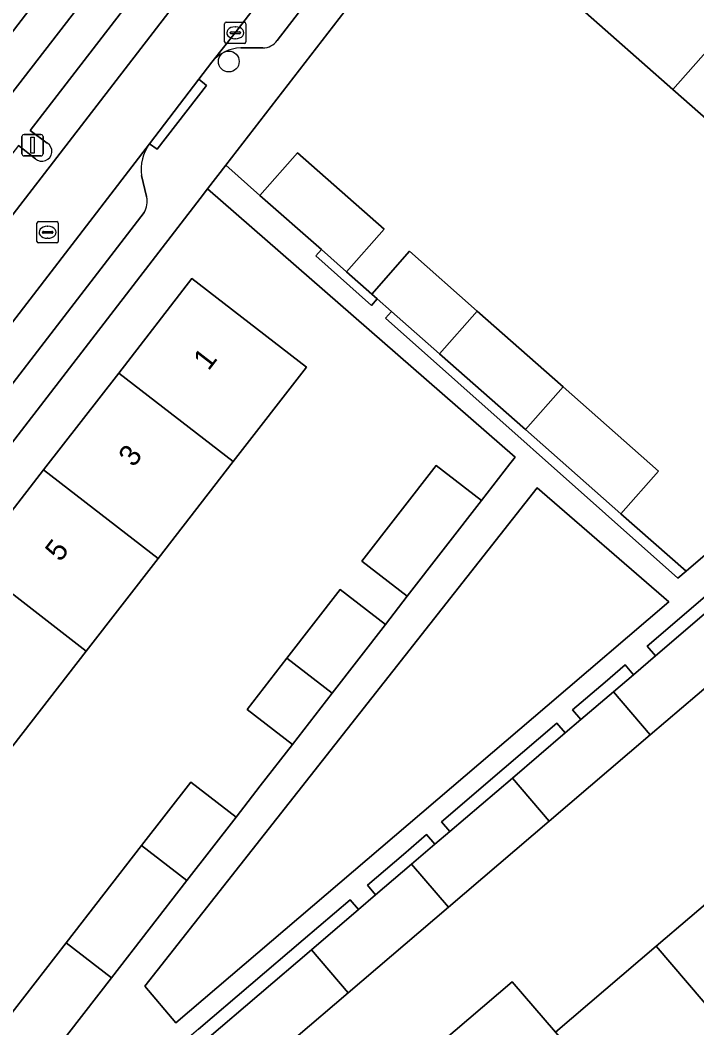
# Model space of a CAD drawing. Extents: x 159039 to 160102, y 381214 to 382524.
# Drawn here: x 159284.46 to 159316.18, y 381529.08 to 381576.34 of the extents above; entities that cross this region are included whole.
import ezdxf

# ---------------------------------------------------------------- set-up
doc = ezdxf.new("R2010")
doc.units = 0
for name, color, linetype in [('IMGEO_Boom', 7, 'Continuous'), ('IMGEO_Erf', 7, 'Continuous'), ('IMGEO_Groenvoorziening', 7, 'Continuous'), ('IMGEO_Kolk', 7, 'Continuous'), ('IMGEO_Lichtmast', 7, 'Continuous'), ('IMGEO_Pand', 7, 'Continuous'), ('IMGEO_Pand_nummerreeks', 7, 'Continuous'), ('IMGEO_Parkeervlak_open', 7, 'Continuous'), ('IMGEO_Rijbaan_lokaal_open', 7, 'Continuous'), ('IMGEO_Rioolput', 7, 'Continuous'), ('IMGEO_Voetpad_open', 7, 'Continuous')]:
    doc.layers.add(name, color=color, linetype=linetype)

msp = doc.modelspace()

# ---------------------------------------------------------------- linework, layer by layer
at = {"layer": 'IMGEO_Boom'}
msp.add_circle((159294.236, 381574.401), 0.489, dxfattribs=at)
at = {"layer": 'IMGEO_Erf'}
for points in [[(159299.551, 381592.96), (159298.091, 381594.079), (159294.348, 381589.194), (159290.532, 381584.215), (159286.641, 381579.137), (159282.958, 381574.331), (159279.168, 381569.384), (159275.191, 381564.195), (159276.512, 381563.173)], [(159284.112, 381542.306), (159280.576, 381537.741), (159277.232, 381533.425), (159271.871, 381537.579), (159275.215, 381541.895), (159278.751, 381546.459), (159282.191, 381550.899), (159285.558, 381555.245), (159289.08, 381559.791), (159292.511, 381564.22), (159297.872, 381560.066), (159294.441, 381555.638), (159290.919, 381551.092), (159287.552, 381546.746)]]:
    msp.add_lwpolyline(points, close=True, dxfattribs=at)
for points in [[(159315.045, 381573.092), (159310.694, 381576.932), (159306.603, 381580.543), (159311.027, 381585.556), (159315.118, 381581.946), (159319.469, 381578.106), (159323.501, 381574.546), (159327.908, 381570.657), (159326.122, 381568.633), (159329.49, 381565.653), (159327.56, 381563.446), (159329.123, 381562.03), (159335.629, 381567.611), (159330.095, 381572.777), (159313.062, 381587.649)], [(159308.113, 381587.579), (159306.856, 381586.072), (159294.094, 381569.533), (159295.697, 381568.119), (159297.465, 381570.121), (159301.524, 381566.539), (159299.757, 381564.536), (159300.936, 381563.495), (159302.703, 381565.499), (159305.875, 381562.699), (159309.907, 381559.139), (159314.377, 381555.194), (159312.61, 381553.192), (159315.671, 381550.49), (159325.662, 381559.061), (159316.821, 381566.857), (159319.159, 381569.462), (159319.078, 381569.533), (159315.045, 381573.092)], [(159296.955, 381546.416), (159299.454, 381549.642), (159301.579, 381547.996), (159302.602, 381549.316), (159300.477, 381550.962), (159303.956, 381555.453), (159306.081, 381553.807), (159307.411, 381555.524), (159307.658, 381555.842), (159293.244, 381568.431), (159292.895, 381567.979), (159271.052, 381539.613)], [(159319.124, 381547.204), (159313.993, 381542.822), (159309.256, 381538.775), (159304.533, 381534.74), (159299.831, 381530.723), (159294.926, 381526.533), (159290.062, 381522.377), (159288.338, 381524.395), (159285.465, 381521.941), (159289.064, 381518.753), (159295.726, 381512.647), (159298.097, 381510.434)], [(159272.188, 381533.437), (159277.302, 381529.172), (159283.05, 381524.08), (159285.339, 381527.035), (159283.214, 381528.681), (159286.611, 381533.065), (159290.148, 381537.63), (159292.453, 381540.606), (159294.578, 381538.96), (159295.713, 381540.424), (159297.219, 381542.368), (159295.094, 381544.014), (159296.955, 381546.416)], [(159318.584, 381527.856), (159313.861, 381523.821), (159309.159, 381519.804), (159304.254, 381515.614), (159299.493, 381511.547), (159295.184, 381516.591), (159299.945, 381520.658), (159304.85, 381524.848), (159302.822, 381527.222), (159307.524, 381531.239), (159309.552, 381528.865), (159314.275, 381532.9), (159319.012, 381536.947)]]:
    msp.add_lwpolyline(points, dxfattribs=at)
at = {"layer": 'IMGEO_Groenvoorziening'}
for points in [[(159299.757, 381564.536), (159298.578, 381565.576), (159298.318, 381565.282), (159300.925, 381562.96), (159301.195, 381563.267), (159300.936, 381563.495)], [(159308.141, 381557.137), (159304.108, 381560.696), (159301.864, 381562.676), (159301.59, 381562.367), (159315.29, 381550.163), (159315.671, 381550.49), (159312.61, 381553.192)], [(159290.297, 381531.025), (159291.758, 381529.315), (159298.155, 381534.78), (159309.155, 381544.179), (159314.868, 381549.06), (159308.694, 381554.412)], [(159317.4, 381549.222), (159319.467, 381550.988), (159319.077, 381551.444), (159317.01, 381549.678), (159313.849, 381546.978), (159314.238, 381546.522)], [(159313.207, 381545.641), (159312.817, 381546.097), (159311.879, 381545.296), (159310.35, 381543.99), (159310.74, 381543.534), (159312.269, 381544.84)], [(159307.532, 381540.793), (159310.01, 381542.911), (159309.621, 381543.367), (159307.142, 381541.249), (159304.211, 381538.745), (159304.601, 381538.289)], [(159303.9, 381537.69), (159303.51, 381538.146), (159302.419, 381537.214), (159300.732, 381535.772), (159301.121, 381535.316), (159302.809, 381536.758)], [(159298.107, 381532.741), (159300.311, 381534.624), (159299.921, 381535.08), (159297.717, 381533.197), (159292.812, 381529.007), (159292.385, 381528.642), (159292.775, 381528.186), (159293.202, 381528.551)]]:
    msp.add_lwpolyline(points, close=True, dxfattribs=at)
at = {"layer": 'IMGEO_Kolk'}
for p, q in [((159294.115, 381576.249), (159294.967, 381576.249)), ((159294.04, 381575.323), (159294.04, 381576.175)), ((159294.342, 381575.792), (159294.74, 381575.792)), ((159294.528, 381576.029), (159294.553, 381576.029)), ((159295.041, 381576.175), (159295.041, 381575.323)), ((159294.299, 381575.743), (159294.299, 381575.755)), ((159294.737, 381575.706), (159294.339, 381575.706)), ((159294.551, 381575.469), (159294.526, 381575.469)), ((159294.783, 381575.755), (159294.783, 381575.743)), ((159294.967, 381575.249), (159294.115, 381575.249))]:
    msp.add_line(p, q, dxfattribs=at)
for points in [[(159294.115, 381576.249), (159294.967, 381576.249)], [(159294.04, 381575.323), (159294.04, 381576.175)], [(159295.041, 381576.175), (159295.041, 381575.323)], [(159294.967, 381575.249), (159294.115, 381575.249)]]:
    msp.add_lwpolyline(points, dxfattribs=at)
for centre, radius, start, end in [((159294.117, 381576.173), 0.0765, 91.552, 178.448), ((159294.117, 381576.173), 0.0765, 91.552, 178.448), ((159294.965, 381576.173), 0.0765, 1.552, 88.448), ((159294.965, 381576.173), 0.0765, 1.552, 88.448), ((159294.339, 381575.752), 0.0403, 85.8775, 175.7526), ((159294.744, 381575.754), 0.0386, 1.7309, 96.639), ((159294.117, 381575.325), 0.0765, 181.552, 268.448), ((159294.117, 381575.325), 0.0765, 181.552, 268.448), ((159294.336, 381575.742), 0.0366, 178.938, 274.7102), ((159294.74, 381575.749), 0.043, 264.8664, 352.4533), ((159294.965, 381575.325), 0.0765, 271.552, 358.448), ((159294.965, 381575.325), 0.0765, 271.552, 358.448)]:
    msp.add_arc(centre, radius, start, end, dxfattribs=at)
for centre, major_axis, ratio, start_param, end_param in [((159294.527, 381575.749), (-0.387, 0.002), 0.722429, 4.712389, 7.853982), ((159294.552, 381575.749), (-0.39, 0.002), 0.717154, 1.570796, 4.712389)]:
    msp.add_ellipse(centre, major_axis=major_axis, ratio=ratio, start_param=start_param, end_param=end_param, dxfattribs=at)
at = {"layer": 'IMGEO_Lichtmast'}
for p, q in [((159284.541, 381570.077), (159284.541, 381570.877)), ((159284.541, 381570.877), (159284.541, 381570.077)), ((159284.641, 381570.977), (159285.431, 381570.977)), ((159285.431, 381570.977), (159284.641, 381570.977)), ((159285.531, 381570.877), (159285.531, 381570.077)), ((159285.531, 381570.077), (159285.531, 381570.877)), ((159285.431, 381569.977), (159284.641, 381569.977)), ((159284.641, 381569.977), (159285.431, 381569.977))]:
    msp.add_line(p, q, dxfattribs=at)
msp.add_lwpolyline([(159284.961, 381570.852), (159285.111, 381570.852), (159285.111, 381570.102), (159284.961, 381570.102), (159284.961, 381570.852)], dxfattribs=at)
for centre, start, end in [((159284.641, 381570.877), 90, 180), ((159284.641, 381570.877), 90, 180), ((159285.431, 381570.877), 0, 90), ((159285.431, 381570.877), 360, 90), ((159284.641, 381570.077), 180, 270), ((159284.641, 381570.077), 180, 270), ((159285.431, 381570.077), 270, 0), ((159285.431, 381570.077), 270, 0)]:
    msp.add_arc(centre, 0.1, start, end, dxfattribs=at)
at = {"layer": 'IMGEO_Pand'}
for points in [[(159282.958, 381574.331), (159286.641, 381579.137), (159281.285, 381583.241), (159277.602, 381578.435)], [(159315.118, 381581.946), (159310.694, 381576.932), (159315.045, 381573.092), (159319.469, 381578.106)], [(159319.078, 381569.533), (159323.501, 381574.546), (159319.469, 381578.106), (159315.045, 381573.092)], [(159297.465, 381570.121), (159295.697, 381568.119), (159298.578, 381565.576), (159299.757, 381564.536), (159301.524, 381566.539)], [(159302.703, 381565.499), (159300.936, 381563.495), (159301.195, 381563.267), (159301.864, 381562.676), (159304.108, 381560.696), (159305.875, 381562.699)], [(159294.441, 381555.638), (159297.872, 381560.066), (159292.511, 381564.22), (159289.08, 381559.791)], [(159305.875, 381562.699), (159304.108, 381560.696), (159308.141, 381557.137), (159309.907, 381559.139)], [(159294.441, 381555.638), (159289.08, 381559.791), (159285.558, 381555.245), (159290.919, 381551.092)], [(159309.907, 381559.139), (159308.141, 381557.137), (159312.61, 381553.192), (159314.377, 381555.194)], [(159302.602, 381549.316), (159306.081, 381553.807), (159303.956, 381555.453), (159300.477, 381550.962)], [(159287.552, 381546.746), (159290.919, 381551.092), (159285.558, 381555.245), (159282.191, 381550.899)], [(159287.552, 381546.746), (159282.191, 381550.899), (159278.751, 381546.459), (159284.112, 381542.306)], [(159301.579, 381547.996), (159299.454, 381549.642), (159296.955, 381546.416), (159299.08, 381544.77)], [(159319.124, 381547.204), (159317.4, 381549.222), (159314.238, 381546.522), (159313.207, 381545.641), (159312.269, 381544.84), (159313.993, 381542.822)], [(159299.08, 381544.77), (159296.955, 381546.416), (159295.094, 381544.014), (159297.219, 381542.368)], [(159313.993, 381542.822), (159312.269, 381544.84), (159310.74, 381543.534), (159310.01, 381542.911), (159307.532, 381540.793), (159309.256, 381538.775)], [(159292.453, 381540.606), (159290.148, 381537.63), (159292.273, 381535.984), (159294.578, 381538.96)], [(159309.256, 381538.775), (159307.532, 381540.793), (159304.601, 381538.289), (159303.9, 381537.69), (159302.809, 381536.758), (159304.533, 381534.74)], [(159286.611, 381533.065), (159288.735, 381531.419), (159292.273, 381535.984), (159290.148, 381537.63)], [(159304.533, 381534.74), (159302.809, 381536.758), (159301.121, 381535.316), (159300.311, 381534.624), (159298.107, 381532.741), (159299.831, 381530.723)], [(159319.012, 381536.947), (159314.275, 381532.9), (159318.584, 381527.856), (159323.321, 381531.903)], [(159286.611, 381533.065), (159283.214, 381528.681), (159285.339, 381527.035), (159288.735, 381531.419)], [(159314.275, 381532.9), (159309.552, 381528.865), (159313.861, 381523.821), (159318.584, 381527.856)], [(159298.107, 381532.741), (159293.202, 381528.551), (159294.926, 381526.533), (159299.831, 381530.723)], [(159309.552, 381528.865), (159307.524, 381531.239), (159302.822, 381527.222), (159304.85, 381524.848), (159309.159, 381519.804), (159313.861, 381523.821)]]:
    msp.add_lwpolyline(points, close=True, dxfattribs=at)
at = {"layer": 'IMGEO_Parkeervlak_open'}
for points in [[(159274.834, 381555.715), (159278.433, 381559.88), (159292.006, 381577.483), (159301.01, 381589.13), (159302.361, 381590.883), (159302.639, 381591.221)], [(159299.695, 381590.335), (159284.933, 381571.171), (159285.73, 381570.578)], [(159304.34, 381588.487), (159303.363, 381587.253), (159294.54, 381575.75), (159293.439, 381574.373)], [(159296.509, 381575.387), (159304.095, 381585.248)], [(159294.802, 381575.04), (159295.833, 381575.036)], [(159290.512, 381570.535), (159281.281, 381558.525), (159268.645, 381542.119), (159266.664, 381539.584)], [(159285.168, 381569.844), (159284.372, 381570.466), (159275.287, 381558.699)], [(159290.385, 381568.062), (159290.146, 381569.053)], [(159278.481, 381553.634), (159279.273, 381553.028), (159290.269, 381567.313)]]:
    msp.add_lwpolyline(points, dxfattribs=at)
for centre, radius, start, end in [((159295.818, 381575.891), 0.855, 271.0048, 323.8747), ((159294.854, 381573.207), 1.833, 91.6303, 140.5204), ((159285.481, 381570.187), 0.464, 227.651, 57.4687), ((159292.162, 381569.341), 2.037, 144.1178, 188.1375), ((159289.429, 381567.827), 0.984, 328.5522, 13.8405)]:
    msp.add_arc(centre, radius, start, end, dxfattribs=at)
at = {"layer": 'IMGEO_Rijbaan_lokaal_open'}
msp.add_lwpolyline([(159290.512, 381570.535), (159292.832, 381573.573), (159293.439, 381574.373), (159294.54, 381575.75), (159303.363, 381587.253), (159304.34, 381588.487), (159304.721, 381588.989), (159305.117, 381589.477), (159303.958, 381590.421), (159302.774, 381591.386), (159302.639, 381591.221), (159302.361, 381590.883), (159301.01, 381589.13), (159292.006, 381577.483), (159278.433, 381559.88), (159274.834, 381555.715), (159266.486, 381544.408), (159264.122, 381541.313), (159263.89, 381541), (159266.26, 381539.068), (159266.664, 381539.584), (159268.645, 381542.119), (159281.281, 381558.525)], close=True, dxfattribs=at)
at = {"layer": 'IMGEO_Rioolput'}
for p, q in [((159285.242, 381565.965), (159285.242, 381566.817)), ((159285.317, 381566.891), (159286.169, 381566.891)), ((159286.243, 381566.817), (159286.243, 381565.965)), ((159285.501, 381566.385), (159285.501, 381566.397)), ((159285.939, 381566.348), (159285.541, 381566.348)), ((159285.544, 381566.434), (159285.942, 381566.434)), ((159285.73, 381566.671), (159285.755, 381566.671)), ((159285.985, 381566.397), (159285.985, 381566.385)), ((159286.169, 381565.891), (159285.317, 381565.891)), ((159285.753, 381566.111), (159285.728, 381566.111))]:
    msp.add_line(p, q, dxfattribs=at)
for points in [[(159285.242, 381565.965), (159285.242, 381566.817)], [(159285.317, 381566.891), (159286.169, 381566.891)], [(159286.243, 381566.817), (159286.243, 381565.965)], [(159286.169, 381565.891), (159285.317, 381565.891)]]:
    msp.add_lwpolyline(points, dxfattribs=at)
for centre, radius, start, end in [((159285.319, 381566.815), 0.0765, 91.552, 178.448), ((159285.319, 381566.815), 0.0765, 91.552, 178.448), ((159286.167, 381566.815), 0.0765, 1.552, 88.448), ((159286.167, 381566.815), 0.0765, 1.552, 88.448), ((159285.541, 381566.394), 0.0403, 85.8775, 175.7526), ((159285.538, 381566.384), 0.0366, 178.938, 274.7102), ((159285.942, 381566.391), 0.043, 264.8664, 352.4533), ((159285.946, 381566.396), 0.0386, 1.7309, 96.639), ((159285.319, 381565.967), 0.0765, 181.552, 268.448), ((159285.319, 381565.967), 0.0765, 181.552, 268.448), ((159286.167, 381565.967), 0.0765, 271.552, 358.448), ((159286.167, 381565.967), 0.0765, 271.552, 358.448)]:
    msp.add_arc(centre, radius, start, end, dxfattribs=at)
for centre, major_axis, ratio, start_param, end_param in [((159285.729, 381566.391), (-0.387, 0.002), 0.722429, 4.712389, 7.853982), ((159285.754, 381566.391), (-0.39, 0.002), 0.717154, 1.570796, 4.712389)]:
    msp.add_ellipse(centre, major_axis=major_axis, ratio=ratio, start_param=start_param, end_param=end_param, dxfattribs=at)
at = {"layer": 'IMGEO_Voetpad_open'}
for points in [[(159299.551, 381592.96), (159276.512, 381563.173), (159275.188, 381561.461), (159273.986, 381559.907), (159272.367, 381557.814), (159262.507, 381545.066)], [(159285.73, 381570.578), (159284.933, 381571.171), (159299.695, 381590.335)], [(159271.052, 381539.613), (159292.895, 381567.979), (159293.244, 381568.431), (159294.094, 381569.533), (159306.856, 381586.072)], [(159304.095, 381585.248), (159296.509, 381575.387)], [(159295.833, 381575.036), (159294.802, 381575.04)], [(159293.439, 381574.373), (159292.832, 381573.573), (159293.184, 381573.274), (159290.873, 381570.285), (159290.512, 381570.535)], [(159284.372, 381570.466), (159285.168, 381569.844)], [(159325.662, 381559.061), (159315.671, 381550.49), (159315.29, 381550.163), (159301.59, 381562.367), (159301.864, 381562.676), (159301.195, 381563.267), (159300.925, 381562.96), (159298.318, 381565.282), (159298.578, 381565.576), (159295.697, 381568.119), (159294.094, 381569.533), (159293.244, 381568.431), (159307.658, 381555.842), (159307.411, 381555.524), (159306.081, 381553.807), (159302.602, 381549.316), (159301.579, 381547.996), (159299.08, 381544.77), (159297.219, 381542.368), (159295.713, 381540.424), (159294.578, 381538.96), (159292.273, 381535.984), (159288.735, 381531.419), (159285.339, 381527.035)], [(159290.146, 381569.053), (159290.385, 381568.062)], [(159290.269, 381567.313), (159279.273, 381553.028), (159278.481, 381553.634)], [(159292.812, 381529.007), (159297.717, 381533.197), (159299.921, 381535.08), (159300.311, 381534.624), (159301.121, 381535.316), (159300.732, 381535.772), (159302.419, 381537.214), (159303.51, 381538.146), (159303.9, 381537.69), (159304.601, 381538.289), (159304.211, 381538.745), (159307.142, 381541.249), (159309.621, 381543.367), (159310.01, 381542.911), (159310.74, 381543.534), (159310.35, 381543.99), (159311.879, 381545.296), (159312.817, 381546.097), (159313.207, 381545.641), (159314.238, 381546.522), (159313.849, 381546.978), (159317.01, 381549.678)]]:
    msp.add_lwpolyline(points, dxfattribs=at)
for points in [[(159292.832, 381573.573), (159290.512, 381570.535), (159290.873, 381570.285), (159293.184, 381573.274)], [(159308.694, 381554.412), (159314.868, 381549.06), (159309.155, 381544.179), (159298.155, 381534.78), (159291.758, 381529.315), (159290.297, 381531.025)]]:
    msp.add_lwpolyline(points, close=True, dxfattribs=at)
for centre, radius, start, end in [((159295.818, 381575.891), 0.855, 271.0048, 323.8747), ((159294.854, 381573.207), 1.833, 91.6303, 140.5204), ((159285.481, 381570.187), 0.464, 227.651, 57.4687), ((159292.162, 381569.341), 2.037, 144.1178, 188.1375), ((159289.429, 381567.827), 0.984, 328.5522, 13.8405)]:
    msp.add_arc(centre, radius, start, end, dxfattribs=at)

# ---------------------------------------------------------------- texts
at = {"layer": 'IMGEO_Pand_nummerreeks'}
for s, p in [('1', (159293.284, 381559.863)), ('3', (159289.774, 381555.333)), ('5', (159286.334, 381550.892))]:
    msp.add_text(s, height=1, rotation=52.2334, dxfattribs=at).set_placement(p)

doc.saveas('drawing.dxf')
